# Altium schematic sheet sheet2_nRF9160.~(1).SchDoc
size A4; SheetNumber: 1; SheetTotal: 2
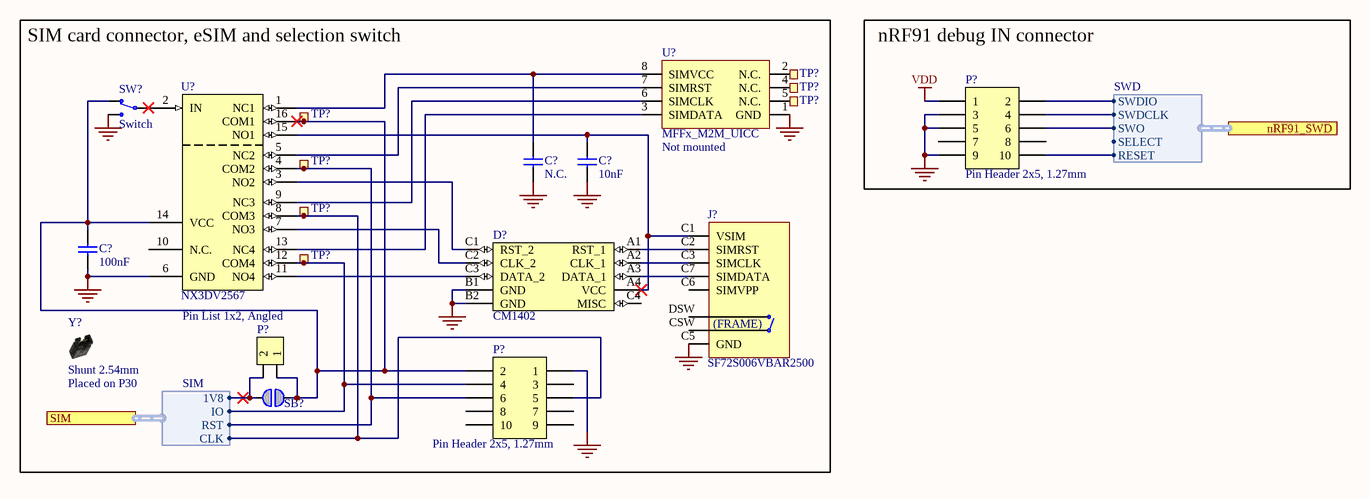
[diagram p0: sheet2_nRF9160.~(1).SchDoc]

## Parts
(Parts that share a designator on the sheet are numbered #1, #2 ... from top to bottom, then left to right.)
C?#1  10nF  [CAPC0603X03L_C]
C?#2  N.C.  [CAPC0603X03L_C_NC]
C?#3  100nF  [CAPC0603X03L_C]
D?  CM1402  [CM1402]
J?  SF72S006VBAR2500  [SF72S006VBAR2500]
P?#1  Pin Header 2x5, 1.27mm  [HDR_2x5-SMD-1.27mm-K]
P?#2  Pin Header 2x5, 1.27mm  [HDR_2x5-SMD-1.27mm]
P?#3  Pin List 1x2, Angled  [LIST_ANG_1x2-SMD-2.54MM]
SB?  Solderbridge  [Solderbridge]  (value not drawn)  (no BOM)
SW?  Switch  [CJS-120xA]
TP?#1  Ø1.0mm,SMD  [TP_SMD_D1.0mm]  (value not drawn)  (no BOM)
TP?#2  Ø1.0mm,SMD  [TP_SMD_D1.0mm]  (value not drawn)  (no BOM)
TP?#3  Ø1.0mm,SMD  [TP_SMD_D1.0mm]  (value not drawn)  (no BOM)
TP?#4  Ø1.5mm,SMD  [TP_SMD_D1.5mm]  (value not drawn)  (no BOM)
TP?#5  Ø1.5mm,SMD  [TP_SMD_D1.5mm]  (value not drawn)  (no BOM)
TP?#6  Ø1.5mm,SMD  [TP_SMD_D1.5mm]  (value not drawn)  (no BOM)
TP?#7  Ø1.5mm,SMD  [TP_SMD_D1.5mm]  (value not drawn)  (no BOM)
U?#1  MFFx_M2M_UICC  Assembly: Not mounted  [SON127P600X90_HS-8N]
U?#2  NX3DV2567  [XQFN40P180X260X50-16N]
Y?  Shunt 2.54mm  Assembly: Placed on P30  [Shunt_2.54mm_Horizontal]

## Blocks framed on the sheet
SIM card connector, eSIM and selection switch: C?#1-C?#3 D? J? P?#2 P?#3 SB? SW? TP?#1-TP?#7 U?#1 U?#2 Y?
nRF91 debug IN connector: P?#1

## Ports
nRF91_SWD (harness SWD), SIM (harness SIM)

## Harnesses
SWD: SWDIO, SWDCLK, SWO, RESET, SELECT
SIM: CLK, IO, 1V8, RST

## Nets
GND: C?#1.2 C?#2.1 C?#3.1 D?.B1(GND) D?.B2(GND) J?.0(GND) J?.C5(GND) P?#1.3 P?#1.5 P?#1.9 P?#2.1 SW?.3(N.O) U?#1.1(GND) U?#2.6(GND)
VDD: P?#1.1
NetC?#1_1: C?#1.1 D?.A4(VCC) J?.C1(VSIM) U?#2.15(NO1)
NetC?#2_2: C?#2.2 U?#1.8(SIMVCC) U?#2.1(NC1)
NetC?#3_2: C?#3.2 P?#2.2 P?#3.1 SB?.2 SW?.1(N.C) TP?#4.1 U?#2.14(VCC) U?#2.16(COM1)
NetD?_A1: D?.A1(RST_1) J?.C2(SIMRST)
NetD?_A2: D?.A2(CLK_1) J?.C3(SIMCLK)
NetD?_A3: D?.A3(DATA_1) J?.C7(SIMDATA)
NetD?_C1: D?.C1(RST_2) U?#2.3(NO2)
NetD?_C2: D?.C2(CLK_2) U?#2.7(NO3)
NetD?_C3: D?.C3(DATA_2) U?#2.11(NO4)
NetP?#1_2: P?#1.2 ; port nRF91_SWD.SWDIO
NetP?#1_4: P?#1.4 ; port nRF91_SWD.SWDCLK
NetP?#1_6: P?#1.6 ; port nRF91_SWD.SWO
NetP?#1_10: P?#1.10 ; port nRF91_SWD.RESET
NetP?#2_4: P?#2.4 TP?#7.1 U?#2.12(COM4) ; port SIM.IO
NetP?#2_5: P?#2.5 TP?#6.1 U?#2.8(COM3) ; port SIM.CLK
NetP?#2_6: P?#2.6 TP?#5.1 U?#2.4(COM2) ; port SIM.RST
NetP?#3_2: P?#3.2 SB?.1 ; port SIM.1V8
NetSW?_2: SW?.2(COM) U?#2.2(IN)
NetTP?#1_1: TP?#1.1 U?#1.2(N.C.)
NetTP?#2_1: TP?#2.1 U?#1.4(N.C.)
NetTP?#3_1: TP?#3.1 U?#1.5(N.C.)
NetU?#1_3: U?#1.3(SIMDATA) U?#2.13(NC4)
NetU?#1_6: U?#1.6(SIMCLK) U?#2.9(NC3)
NetU?#1_7: U?#1.7(SIMRST) U?#2.5(NC2)

Not connected (* = marked no-connect by the designer): D? C4(MISC); J? C6(SIMVPP) CSW DSW; P?#1 7 8; P?#2 3 7 8 9 10; U?#2 10(N.C.)

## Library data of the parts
C?#1 = C0201-10n: Capacitor, X7R, ±10%; Manufacturer: N.A.; Part number IPS: 00000003480; Note: 10V; Pad Count: 2
C?#2 = C0201-N.C.: Not mounted; Manufacturer: N.A.; Note: Chip Cap; Assembly: Not mounted; Pad Count: 2
C?#3 = C0201-100n: Capacitor, X5R, ±10%; Manufacturer: N.A.; Part number IPS: 00000001248, 00000002505; Note: 16V; Pad Count: 2
D? = CM1402: EMI Network Filter Arrays SIM CARD EMI FILTER WITH ESD PROTECTION; Manufacturer: ON Semiconductor; Manufacturer Part Number: CM1402-03CP; Part number IPS: 00000009949; Note: N.A.; Pad Count: 10
J? = SF72S006VBAR2500: n 8 (6 + 2) Position Card Connector NANO SIM Surface Mount, Right Angle Gold; Manufacturer: JAE Electronics; Part number IPS: 00000009956; Note: N.A.; Pad Count: 8
P?#1 = Pin Header 2x5 SMD, 1.27mm, KS: Pin Header 2x5, 1.27mm (50mil), SMD, Keying Shroud; Manufacturer: W-CON; Manufacturer Part Number: 3132-10MS0BK00R1; Part number IPS: 00000009968; Note: N.A.; Artikkelnr Noca: 55010009; Pad Count: 10
P?#2 = Pin Header 2x5 SMD, 1.27mm: Pin Header 2x5, 1.27mm (50mil), SMD; Manufacturer: W-CON; Manufacturer Part Number: 1325-1205S0M078R1; Part number IPS: 00000009970; Note: N.A.; Artikkelnr Noca: 55019196; Pad Count: 10
P?#3 = Pin List Ang 1x2 SMD, 2.54mm: Pin List 1x2, 2.54mm (100mil), Right Angled, SMD; Manufacturer: W-CON; Manufacturer Part Number: 1125B-1102S0Z135R2; Part number IPS: 00000009972; Note: N.A.; Artikkelnr Noca: 55010023; Pad Count: 2
SB? = Solderbridge: Manufacturer: N.A.; Pad Count: 2
SW? = CJS-1200TA: SMD slide Switch (ON-ON); Manufacturer: Copal Electronics Inc; Part number IPS: 00000009982; Note: N.A.; Artikkelnr Noca: 50019068; Pad Count: 3
TP?#1-TP?#3 = TP_SMD_Ø1.0MM: 1.0mm circular SMD testpad; Manufacturer: Nordic Semiconductor; Manufacturer Part Number: N.A.; Pad Count: 1
TP?#4-TP?#7 = TP_SMD_Ø1.5MM: 1.5mm circular SMD testpad; Manufacturer: Nordic Semiconductor; Manufacturer Part Number: N.A.; Pad Count: 1
U?#1 = M2M_UICC: M2M UICC SIM Card; Manufacturer: N.A.; Pad Count: 8
U?#2 = NX3DV2567GU: Low-ohmic four-pole double-throw analog switch; Manufacturer: NXP Semiconductors; Part number IPS: 00000007816; Note: N.A.; Artikkelnr Noca: 15079317; Pad Count: 16
Y? = SHUNT JUMPER 2.54mm BLACK GOLD Horizontal (obsolete): Shunt Jumper 2.54mm Black; Manufacturer: N.A.; Part number IPS: 00000001916; Note: SHUNT JUMPER .1" BLACK GOLD, h=6.00mm, w=5.00mm; Artikkelnr Noca: 56099001; Pad Count: 2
